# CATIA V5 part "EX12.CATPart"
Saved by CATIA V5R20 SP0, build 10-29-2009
Part number: EX12
Bounding box of the stored display mesh (mm): x -42 to 60.611, y -47 to 91.35, z 0 to 15
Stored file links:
  E:\Nouveau dossier\tarek\mécaniquee\Catia\TP 0\EX12.CATPart
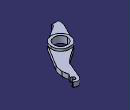
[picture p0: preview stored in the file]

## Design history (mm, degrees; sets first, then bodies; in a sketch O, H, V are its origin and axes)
Set1
  DatumSurface1 to DatumSurface26
Body1 (main body)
